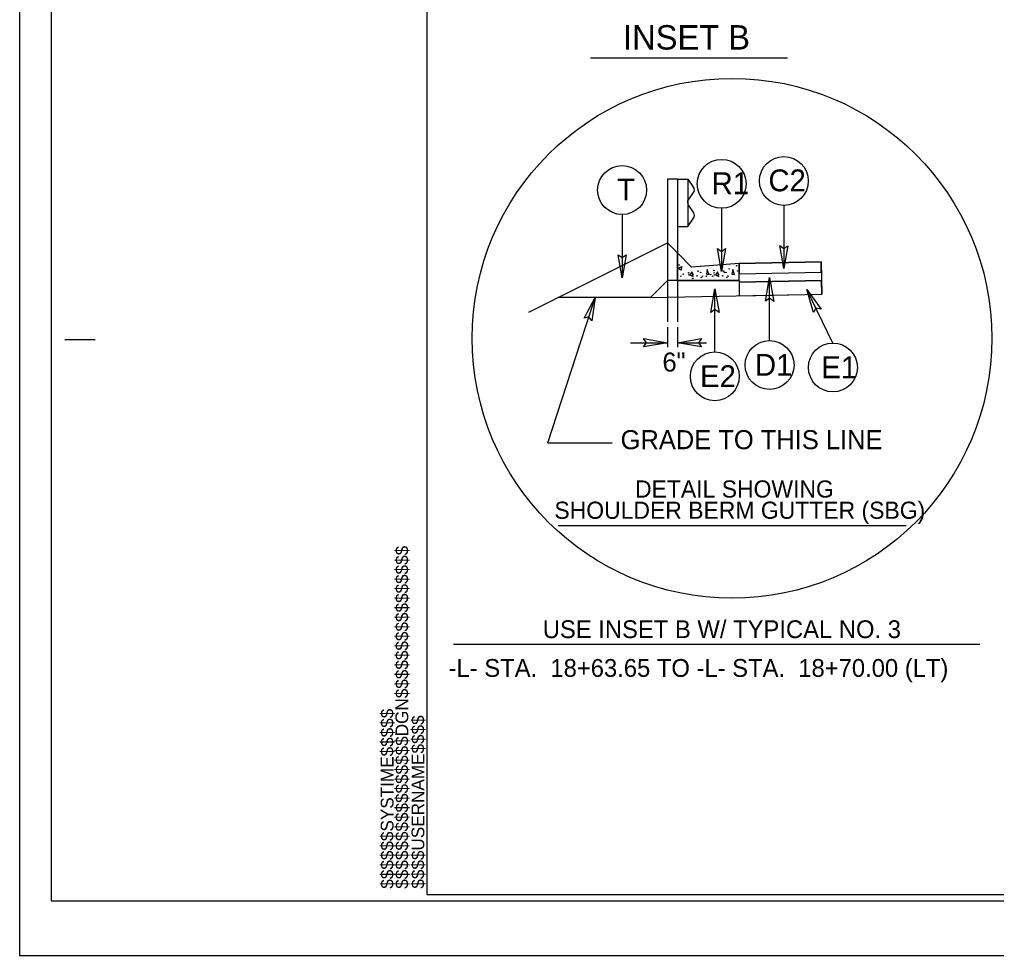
# Model space of a CAD drawing. Extents: x 573732 to 574187, y -53389 to -53257.
# Drawn here: x 573782.22 to 573830.28, y -53388.95 to -53342.91 of the extents above; entities that cross this region are included whole.
import ezdxf

# ---------------------------------------------------------------- set-up
doc = ezdxf.new("R2010")
doc.units = 0
for name, color, linetype in [('Prop Dimension', 7, 'Continuous'), ('Prop Shade Light', 7, 'Continuous'), ('Prop Shade Medium', 7, 'Continuous'), ('Prop Terminator CELL', 7, 'Continuous'), ('Sheet Cutting Line CELL', 7, 'Continuous'), ('Sheet Plot Border Inside CELL', 7, 'Continuous'), ('Sheet Plot Border Outside CELL', 7, 'Continuous'), ('Sheet Typical CELL', 7, 'Continuous'), ('Typical ID Circle CELL', 7, 'Continuous'), ('Typical Shoulder Slope CELL', 7, 'Continuous'), ('Typical Shoulder Slope Information CELL', 7, 'Continuous'), ('Typical Slope Point Local CELL', 7, 'Continuous'), ('Typical Terminator CELL', 7, 'Continuous'), ('Typical Text General CELL', 7, 'Continuous'), ('Typical Text ID Circle CELL', 7, 'Continuous'), ('Typical Text Label CELL', 7, 'Continuous')]:
    doc.layers.add(name, color=color, linetype=linetype)

msp = doc.modelspace()

# ---------------------------------------------------------------- linework, layer by layer
at = {"layer": 'Prop Dimension'}
for p, q in [((573808.211, -53363.738), (573810.531, -53356.593)), ((573814.091, -53358.037), (573814.091, -53359.023)), ((573814.591, -53358.037), (573814.591, -53359.023)), ((573812.278, -53358.809), (573814.091, -53358.809)), ((573814.591, -53358.809), (573816.006, -53358.809)), ((573808.211, -53363.738), (573811.368, -53363.738))]:
    msp.add_line(p, q, dxfattribs=at)
at = {"layer": 'Prop Shade Light'}
for p, q in [((573817.628, -53354.941), (573817.628, -53355.42)), ((573821.66, -53355.338), (573821.649, -53354.837)), ((573817.628, -53355.42), (573821.66, -53355.338))]:
    msp.add_line(p, q, dxfattribs=at)
msp.add_lwpolyline([(573821.649, -53354.837), (573817.628, -53354.92), (573817.618, -53354.92)], dxfattribs=at)
msp.add_ellipse((573817.618, -53354.941), major_axis=(0, 0.0209), ratio=0.5, start_param=4.712389, end_param=6.268072, dxfattribs=at)
at = {"layer": 'Prop Shade Medium'}
for p, q in [((573821.668, -53355.754), (573817.628, -53355.837)), ((573817.628, -53355.837), (573817.628, -53356.504)), ((573821.682, -53356.421), (573821.668, -53355.754)), ((573817.628, -53356.504), (573821.682, -53356.421))]:
    msp.add_line(p, q, dxfattribs=at)
at = {"layer": 'Prop Terminator CELL'}
for points in [[(573816.953, -53354.179), (573816.759, -53355.304), (573816.559, -53354.173), (573816.759, -53354.316)], [(573820.012, -53354.039), (573819.819, -53355.164), (573819.619, -53354.033), (573819.819, -53354.177)], [(573812.056, -53354.485), (573811.862, -53355.61), (573811.662, -53354.479), (573811.862, -53354.622)], [(573809.999, -53357.604), (573810.531, -53356.593), (573810.372, -53357.731), (573810.226, -53357.533)]]:
    msp.add_lwpolyline(points, close=True, dxfattribs=at)
at = {"layer": 'Sheet Cutting Line CELL'}
for p, q in [((573782.222, -53256.948), (573782.222, -53388.948)), ((573782.222, -53388.948), (573984.302, -53388.948))]:
    msp.add_line(p, q, dxfattribs=at)
at = {"layer": 'Sheet Plot Border Inside CELL'}
msp.add_lwpolyline([(573983.762, -53259.642), (573783.782, -53259.642), (573783.782, -53386.254), (573983.762, -53386.254)], close=True, dxfattribs=at)
at = {"layer": 'Sheet Plot Border Outside CELL'}
msp.add_lwpolyline([(573984.302, -53256.948), (573782.222, -53256.948), (573782.222, -53388.948), (573984.302, -53388.948)], close=True, dxfattribs=at)
at = {"layer": 'Sheet Typical CELL'}
for p, q in [((573784.442, -53358.648), (573785.942, -53358.648)), ((573802.262, -53385.948), (573802.262, -53385.948)), ((573802.262, -53385.948), (573802.262, -53385.948)), ((573802.262, -53385.948), (573802.262, -53385.948)), ((573802.262, -53385.948), (573802.262, -53385.948)), ((573802.262, -53385.948), (573802.262, -53385.948)), ((573802.262, -53385.948), (573802.262, -53385.948))]:
    msp.add_line(p, q, dxfattribs=at)
msp.add_lwpolyline([(573982.262, -53259.948), (573802.262, -53259.948), (573802.262, -53385.948), (573982.262, -53385.948)], close=True, dxfattribs=at)
msp.add_lwpolyline([(573806.762, -53385.948), (573806.762, -53385.948)], dxfattribs=at)
at = {"layer": 'Typical ID Circle CELL'}
for p, q in [((573816.759, -53352.197), (573816.759, -53355.304)), ((573819.819, -53352.057), (573819.819, -53355.164)), ((573811.862, -53352.503), (573811.862, -53355.61)), ((573819.117, -53358.704), (573819.117, -53355.597)), ((573816.423, -53359.259), (573816.423, -53356.152)), ((573822.233, -53358.824), (573820.949, -53356.188))]:
    msp.add_line(p, q, dxfattribs=at)
for centre in [(573816.759, -53350.995), (573819.819, -53350.855), (573811.862, -53351.301), (573819.117, -53359.906), (573822.233, -53360.026), (573816.423, -53360.461)]:
    msp.add_circle(centre, 1.202, dxfattribs=at)
at = {"layer": 'Typical Shoulder Slope CELL'}
for p, q in [((573814.591, -53354.396), (573814.091, -53353.896)), ((573817.617, -53354.92), (573821.649, -53354.838)), ((573821.649, -53354.837), (573821.682, -53356.421)), ((573817.628, -53355.42), (573821.66, -53355.338)), ((573817.628, -53355.757), (573814.088, -53355.757)), ((573817.628, -53355.837), (573821.668, -53355.754)), ((573817.628, -53355.757), (573817.628, -53356.504)), ((573813.252, -53356.593), (573821.686, -53356.421))]:
    msp.add_line(p, q, dxfattribs=at)
at = {"layer": 'Typical Slope Point Local CELL'}
for p, q in [((573814.591, -53350.759), (573814.091, -53350.759)), ((573814.091, -53350.759), (573814.091, -53355.757)), ((573814.591, -53350.759), (573814.591, -53355.757)), ((573814.591, -53350.759), (573815.091, -53350.759)), ((573815.091, -53350.759), (573815.091, -53353.091)), ((573815.091, -53350.759), (573815.382, -53351.167)), ((573815.091, -53351.831), (573815.382, -53351.423)), ((573815.091, -53351.925), (573815.091, -53351.831)), ((573815.091, -53351.925), (573815.091, -53352.019)), ((573815.091, -53352.019), (573815.382, -53352.427)), ((573815.091, -53353.091), (573815.382, -53352.683)), ((573814.591, -53353.091), (573815.091, -53353.091)), ((573807.281, -53357.301), (573814.091, -53353.896)), ((573814.591, -53355.757), (573814.591, -53354.396)), ((573815.282, -53355.087), (573814.591, -53354.396)), ((573814.628, -53355.156), (573814.783, -53355.066)), ((573814.766, -53355.249), (573814.628, -53355.156)), ((573814.783, -53355.066), (573814.766, -53355.249)), ((573817.617, -53354.92), (573815.282, -53355.087)), ((573816.047, -53355.211), (573816.012, -53355.439)), ((573816.133, -53355.452), (573816.047, -53355.211)), ((573817.302, -53355.211), (573817.268, -53355.439)), ((573817.389, -53355.452), (573817.302, -53355.211)), ((573817.628, -53354.919), (573817.628, -53354.919)), ((573817.628, -53355.757), (573817.628, -53354.941)), ((573815.301, -53355.324), (573815.197, -53355.475)), ((573815.197, -53355.475), (573815.364, -53355.555)), ((573815.364, -53355.555), (573815.301, -53355.324)), ((573816.012, -53355.439), (573816.133, -53355.452)), ((573816.557, -53355.324), (573816.453, -53355.475)), ((573816.453, -53355.475), (573816.62, -53355.555)), ((573816.62, -53355.555), (573816.557, -53355.324)), ((573817.268, -53355.439), (573817.389, -53355.452)), ((573813.252, -53356.593), (573814.088, -53355.757)), ((573814.591, -53355.757), (573814.091, -53355.757)), ((573814.091, -53355.757), (573814.091, -53357.785)), ((573814.591, -53355.757), (573817.628, -53355.757)), ((573814.591, -53355.757), (573814.591, -53357.785)), ((573813.252, -53356.593), (573808.696, -53356.593))]:
    msp.add_line(p, q, dxfattribs=at)
msp.add_circle((573817.271, -53358.591), 12.784, dxfattribs=at)
for centre, major_axis, start_param, end_param in [((573815.338, -53351.295), (0, -0.156), 0.61067, 2.530675), ((573815.338, -53352.555), (0, 0.156), 3.751819, 5.672217), ((573817.618, -53354.941), (0, 0.0209), 4.712389, 6.31893)]:
    msp.add_ellipse(centre, major_axis=major_axis, ratio=0.5, start_param=start_param, end_param=end_param, dxfattribs=at)
for centre in [(573814.656, -53354.985), (573817.13, -53355.175), (573817.5, -53355.025), (573814.754, -53355.534), (573814.874, -53355.432), (573815.133, -53355.375), (573815.15, -53355.476), (573815.328, -53355.649), (573815.356, -53355.444), (573815.552, -53355.523), (573815.599, -53355.29), (573815.725, -53355.348), (573815.758, -53355.603), (573815.815, -53355.534), (573816.01, -53355.534), (573816.13, -53355.432), (573816.224, -53355.451), (573816.321, -53355.543), (573816.378, -53355.256), (573816.389, -53355.375), (573816.406, -53355.476), (573816.612, -53355.444), (573816.808, -53355.523), (573816.855, -53355.29), (573816.905, -53355.352), (573816.981, -53355.348), (573817.014, -53355.603), (573817.071, -53355.534), (573817.538, -53355.277)]:
    msp.add_ellipse(centre, major_axis=(0, 0.0161), ratio=0.5, dxfattribs=at)
at = {"layer": 'Typical Terminator CELL'}
for points in [[(573818.915, -53356.769), (573819.117, -53355.597), (573819.325, -53356.775), (573819.117, -53356.626)], [(573816.221, -53357.324), (573816.423, -53356.152), (573816.632, -53357.331), (573816.423, -53357.181)], [(573821.281, -53357.33), (573820.949, -53356.188), (573821.652, -53357.156), (573821.4, -53357.113)], [(573815.763, -53359.011), (573814.591, -53358.809), (573815.769, -53358.6), (573815.62, -53358.809)], [(573812.919, -53358.607), (573814.091, -53358.809), (573812.913, -53359.017), (573813.062, -53358.809)]]:
    msp.add_lwpolyline(points, close=True, dxfattribs=at)
at = {"layer": 'Typical Text General CELL'}
msp.add_line((573808.724, -53367.808), (573825.844, -53367.808), dxfattribs=at)
at = {"layer": 'Typical Text Label CELL'}
for p, q in [((573810.3, -53344.792), (573819.998, -53344.792)), ((573803.574, -53373.635), (573829.453, -53373.635))]:
    msp.add_line(p, q, dxfattribs=at)

# ---------------------------------------------------------------- texts
at = {"layer": 'Sheet Typical CELL'}
for s, p in [('$$$$$$$$$$$$$$$$DGN$$$$$$$$$$$$$$$$', (573801.344, -53385.665)), ('$$$$$$SYSTIME$$$$$', (573800.618, -53385.665)), ('$$$$USERNAME$$$$', (573802.133, -53385.663))]:
    msp.add_text(s, height=0.63, rotation=90, dxfattribs=at).set_placement(p)
at = {"layer": 'Typical Shoulder Slope Information CELL'}
msp.add_text('6"', height=0.9375, rotation=1.1457, dxfattribs=at).set_placement((573813.856, -53360.236))
at = {"layer": 'Typical Text General CELL'}
msp.add_text('GRADE TO THIS LINE', height=0.9375, dxfattribs=at).set_placement((573811.788, -53364.047))
at = {"layer": 'Typical Text ID Circle CELL'}
for s, p in [('R1', (573816.267, -53351.503)), ('C2', (573819.061, -53351.363)), ('T', (573811.618, -53351.809)), ('D1', (573818.4, -53360.437)), ('E1', (573821.662, -53360.557)), ('E2', (573815.698, -53360.992))]:
    msp.add_text(s, height=1.076, dxfattribs=at).set_placement(p)
at = {"layer": 'Typical Text Label CELL'}
msp.add_text('INSET B  ', height=1.2002, rotation=360, dxfattribs=at).set_placement((573811.911, -53344.39))
for s, height, p in [('DETAIL SHOWING', 0.84375, (573812.499, -53366.426)), ('SHOULDER BERM GUTTER (SBG)', 0.84375, (573808.532, -53367.47)), ('USE INSET B W/ TYPICAL NO. 3', 0.875, (573807.96, -53373.339)), ('-L- STA.  18+63.65 TO -L- STA.  18+70.00 (LT)', 0.875, (573803.329, -53375.244))]:
    msp.add_text(s, height=height, dxfattribs=at).set_placement(p)

doc.saveas('drawing.dxf')
